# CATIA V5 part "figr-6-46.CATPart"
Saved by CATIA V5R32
Part number: Part1
Bounding box of the stored display mesh (mm): x 0 to 100, y -60 to 60, z -50 to 50
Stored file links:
  D:\PROJECTS\Project 2022\CATIA V5 6R 2022\Resources\Part Files\c06_catia_v5_6r2022_prt\figr-6-46.CATPart
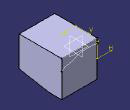
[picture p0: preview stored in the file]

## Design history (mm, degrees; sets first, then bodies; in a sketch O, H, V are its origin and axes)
Body1 (main body)
  Sketch1 on yz-plane, origin (0, 0, 0), H (0, 1, 0), V (0, 0, 1)
    line L1 (60, 50) -> (60, -50)
    line L2 (60, -50) -> (25, -50)
    line L3 (-60, -35) -> (-60, 50)
    line L4 (-60, 50) -> (60, 50)
    point P2 (60, -50)
    point P3 (-60, -50)
    line L5 (25, -50) -> (-60, -35)
    point P5 (25, -50)
    point P6 (-60, -35)
    length L1 = 100
    distance P2 P3 = 120
    distance P5 P3 = 85
    distance P6 P3 = 15
    vertical: L1 V, L3 V
    horizontal: L2 H, L4 H
    equidistance: L1 L3 O, L2 L4 O
    coincidence: L2 P3, L3 P3
  Pad1: profile Sketch1, direction (1, 0, 0), length 100
  Sketch2 on face of Pad1 from Sketch1.L1, origin (0, 60, 0), H (-1, 0, 0), V (0, 0, 1)
    spline S1 through (-100, 18.28) (-85.0256, 26.4663) (-71, 29) (-63.0256, 32.4663) (-31, 39) (-16, 39) (0, 37.4663)
    reference projected line E1 (-100, -50) -> (-100, 50) from edge [face of Pad1 from Sketch1.L1 | end face of Pad1]
    reference projected line E2 (0, -50) -> (0, 50) from edge [start face of Pad1 | face of Pad1 from Sketch1.L1]
    point P1 (0, 37.4663)
    point P2 (-100, 18.28)
    coincidence: P1 V, P2 E1, P1 E2
  Sketch3 on face of Pad1 from Sketch1.L4, origin (0, 0, 50), H (1, 0, 0), V (0, 1, 0)
    projected line E1 (0, 60) -> (100, 60) from Sketch2.S1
